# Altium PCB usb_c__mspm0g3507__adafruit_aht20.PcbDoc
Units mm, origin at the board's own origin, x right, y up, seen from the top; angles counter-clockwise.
Board outline 92 x 60 mm, 2 copper layers (Top, Bottom), stack 0 mm thick; 38 components, 33 nets, 190 pads, 53 vias.
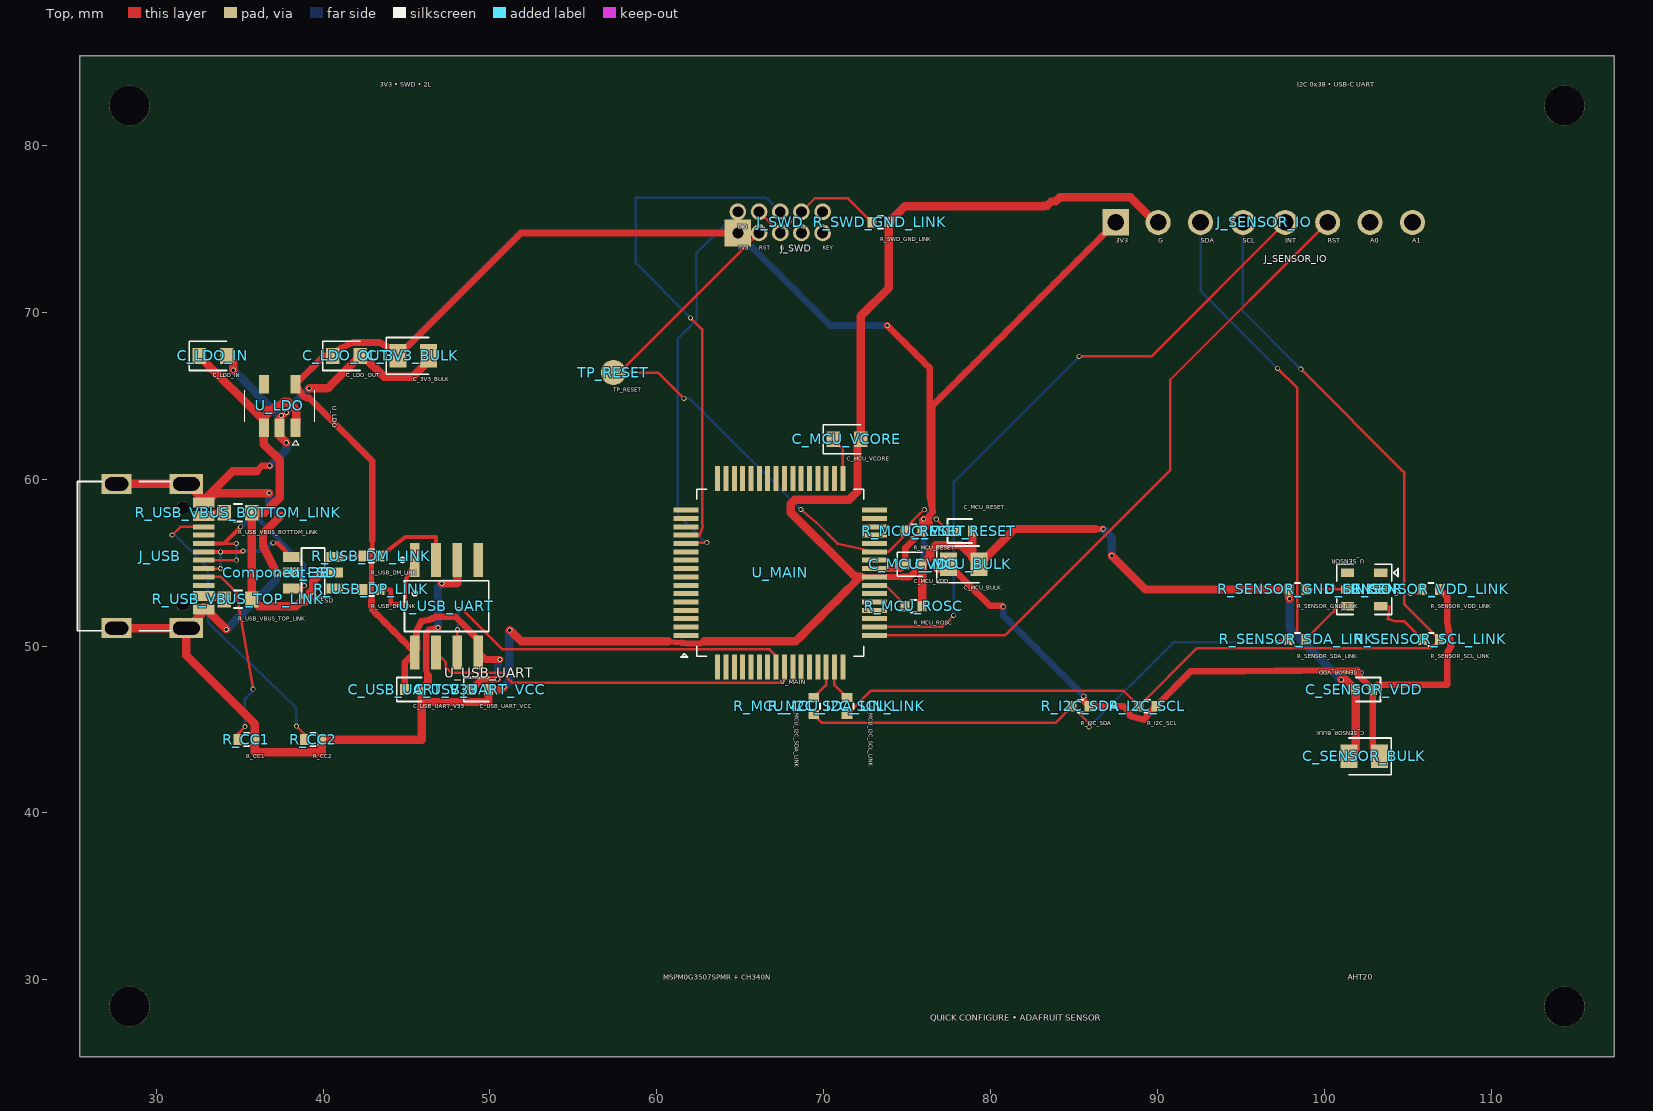
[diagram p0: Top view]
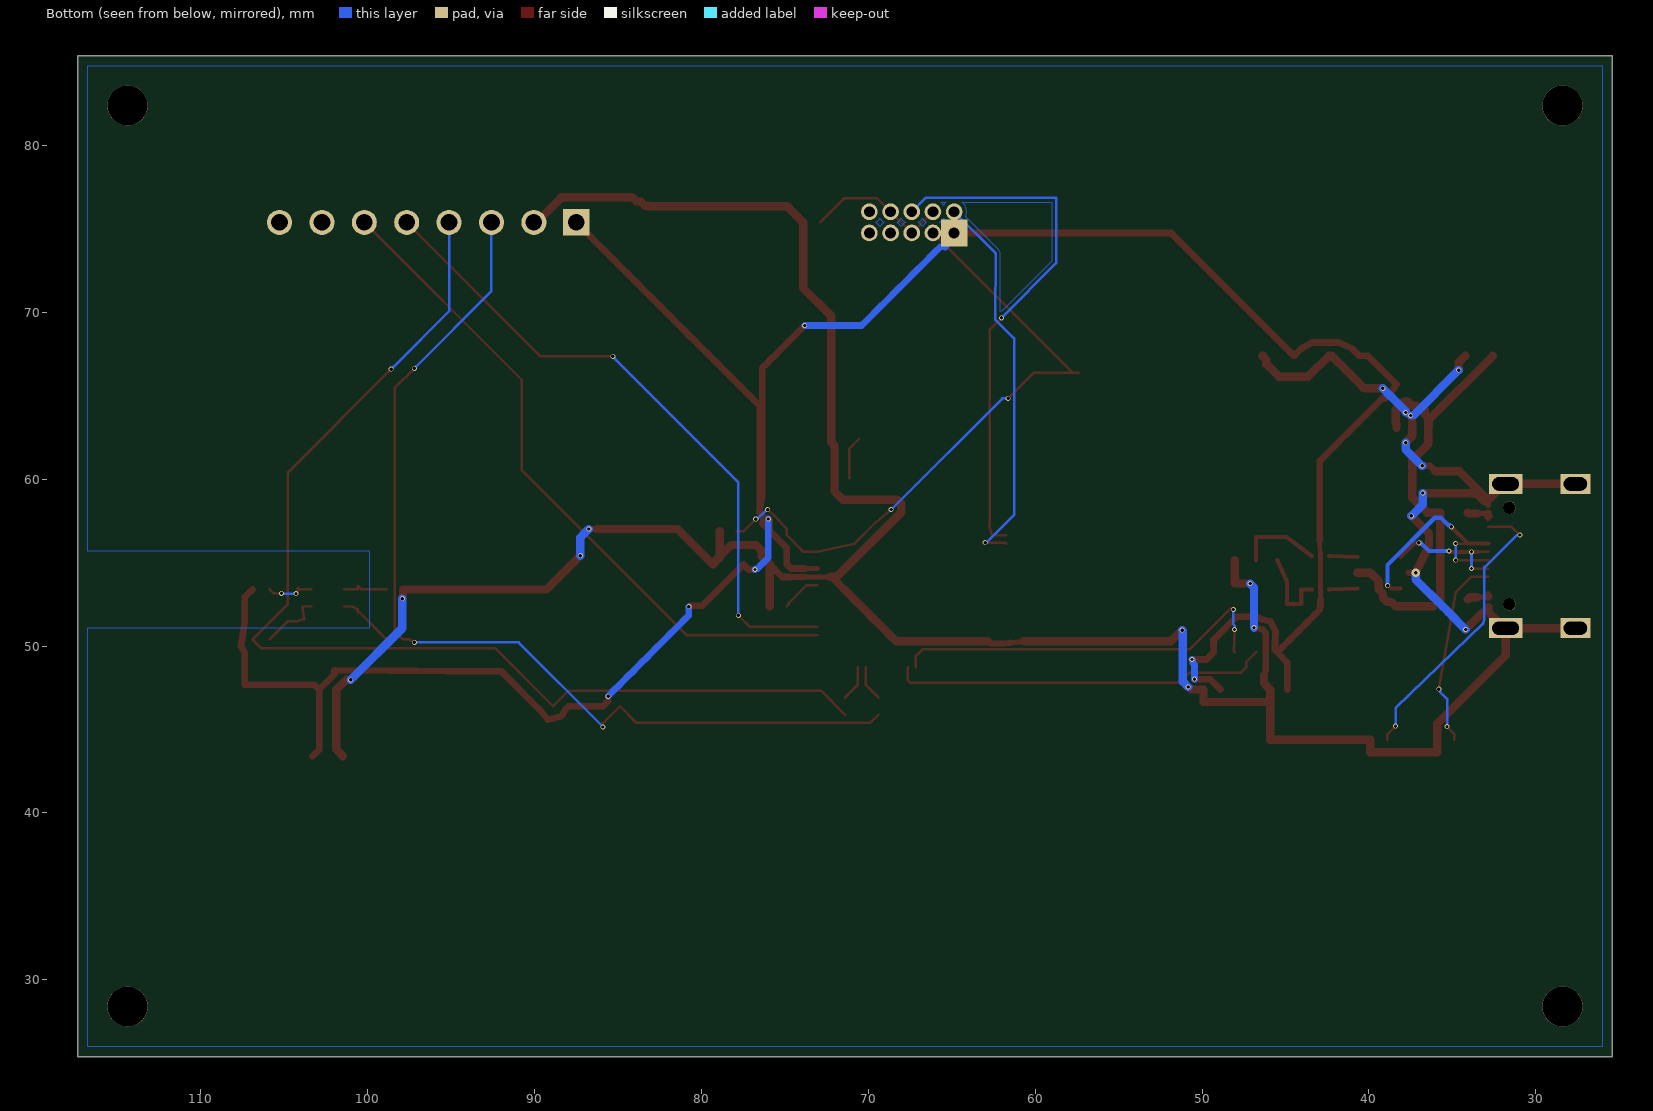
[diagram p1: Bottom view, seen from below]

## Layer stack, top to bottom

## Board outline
25.4,85.4 117.4,85.4 117.4,25.4 25.4,25.4

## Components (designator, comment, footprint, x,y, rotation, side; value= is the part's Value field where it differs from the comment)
C_3V3_BULK "" TSCIRCUIT-2.8500x1.4000mm 45.4,67.4 r0 top
C_LDO_IN "" TSCIRCUIT-2.4500x0.9500mm 33.4,67.4 r0 top
C_LDO_OUT "" TSCIRCUIT-2.4500x0.9500mm 41.4,67.4 r0 top
C_MCU_BULK "" TSCIRCUIT-2.8500x1.4000mm 78.4,54.9 r0 top
C_MCU_RESET "" TSCIRCUIT-1.5600x0.6400mm 78.4,56.9 r0 top
C_MCU_VCORE "" TSCIRCUIT-2.4500x0.9500mm 71.4,62.4 r0 top
C_MCU_VDD "" TSCIRCUIT-1.5600x0.6400mm 75.4,54.9 r0 top
C_SENSOR_BULK "" TSCIRCUIT-2.8500x1.4000mm 102.4,43.4 r180 top
C_SENSOR_VDD "" TSCIRCUIT-1.5600x0.6400mm 102.4,47.4 r180 top
C_USB_UART_V33 "" TSCIRCUIT-1.5600x0.6400mm 45.4,47.4 r0 top
C_USB_UART_VCC "" TSCIRCUIT-1.5600x0.6400mm 49.4,47.4 r0 top
Component-38 "" TSCIRCUIT-0.5000x0.5000mm 37.2,54.4 r0 top
J_SENSOR_IO "" TSCIRCUIT-19.2800x1.5000mm 96.4,75.4 r0 top
J_SWD "" TSCIRCUIT-6.0800x2.2700mm 67.4,75.4 r0 top
J_USB "" TSCIRCUIT-6.7732x9.8502mm 30.113,55.4 r90 top
R_CC1 "" TSCIRCUIT-1.5600x0.6400mm 35.4,44.4 r0 top
R_CC2 "" TSCIRCUIT-1.5600x0.6400mm 39.4,44.4 r0 top
R_I2C_SCL "" TSCIRCUIT-1.5600x0.6400mm 89.4,46.4 r0 top
R_I2C_SDA "" TSCIRCUIT-1.5600x0.6400mm 85.4,46.4 r0 top
R_MCU_I2C_SCL_LINK "" TSCIRCUIT-0.6400x1.5600mm 71.4,46.4 r270 top
R_MCU_I2C_SDA_LINK "" TSCIRCUIT-0.6400x1.5600mm 69.4,46.4 r270 top
R_MCU_RESET "" TSCIRCUIT-1.5600x0.6400mm 75.4,56.9 r0 top
R_MCU_ROSC "" TSCIRCUIT-1.5600x0.6400mm 75.4,52.4 r0 top
R_SENSOR_GND_LINK "" TSCIRCUIT-1.5600x0.6400mm 98.4,53.4 r0 top
R_SENSOR_SCL_LINK "" TSCIRCUIT-1.5600x0.6400mm 106.4,50.4 r0 top
R_SENSOR_SDA_LINK "" TSCIRCUIT-1.5600x0.6400mm 98.4,50.4 r0 top
R_SENSOR_VDD_LINK "" TSCIRCUIT-1.5600x0.6400mm 106.4,53.4 r0 top
R_SWD_GND_LINK "" TSCIRCUIT-1.5600x0.6400mm 73.4,75.4 r0 top
R_USB_DM_LINK "" TSCIRCUIT-1.5600x0.6400mm 42.9,55.4 r0 top
R_USB_DP_LINK "" TSCIRCUIT-1.5600x0.6400mm 42.9,53.4 r0 top
R_USB_VBUS_BOTTOM_LINK "" TSCIRCUIT-2.4500x0.9500mm 34.9,58 r0 top
R_USB_VBUS_TOP_LINK "" TSCIRCUIT-2.4500x0.9500mm 34.9,52.8 r0 top
TP_RESET "" TSCIRCUIT-1.5000x1.5000mm 57.4,66.4 r0 top
U_ESD "" TSCIRCUIT-3.6000x2.5000mm 39.4,54.4 r0 top
U_LDO "" TSCIRCUIT-2.5000x3.7000mm 37.4,64.4 r270 top
U_MAIN "" TSCIRCUIT-12.8000x12.8000mm 67.4,54.4 r0 top
U_SENSOR "" TSCIRCUIT-2.8000x2.5000mm 102.4,53.4 r0 top
U_USB_UART "" TSCIRCUIT-4.3840x7.5712mm 47.4,52.4 r0 top

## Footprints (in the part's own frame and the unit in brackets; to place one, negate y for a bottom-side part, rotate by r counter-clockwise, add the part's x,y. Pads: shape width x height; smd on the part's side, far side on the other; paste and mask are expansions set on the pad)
TSCIRCUIT-0.5000x0.5000mm [mm]
TSCIRCUIT-0.6400x1.5600mm [mm]
  rect 0.54x0.64 smd: 1(-0.51,0) 2(0.51,0)
  silkscreen extent -0.15,-0.38 0.15,0.38
TSCIRCUIT-1.5000x1.5000mm [mm]
  round 1.5 smd: 1(0,0)
TSCIRCUIT-1.5600x0.6400mm [mm]
  rect 0.54x0.64 smd: 1(-0.51,0) 2(0.51,0)
  silkscreen extent -0.98,-0.72 0.51,0.72
TSCIRCUIT-2.4500x0.9500mm [mm]
  rect 0.8x0.95 smd: 1(-0.825,0) 2(0.825,0)
  silkscreen extent -1.42,-0.87 0.82,0.87
TSCIRCUIT-2.5000x3.7000mm [mm]
  rect 1.1x0.6 smd: 1(1.3,0.95) 2(1.3,0) 3(1.3,-0.95) 4(-1.3,-0.95) 5(-1.3,0.95)
  silkscreen extent -0.95,-2.1 2.35,2.1
TSCIRCUIT-2.8000x2.5000mm [mm]
  rect 0.8x0.5 smd: 1(1,1) 2(1,0) 3(1,-1) 4(-1,-1) 5(-1,0) 6(-1,1)
  silkscreen extent -1.65,-1.5 2.02,1.5
TSCIRCUIT-2.8500x1.4000mm [mm]
  rect 1.025x1.4 smd: 1(-0.913,0) 2(0.913,0)
  silkscreen extent -1.63,-1.1 0.91,1.1
TSCIRCUIT-3.6000x2.5000mm [mm]
  rect 1x0.6 smd: 1(-1.3,-0.95) 2(-1.3,0) 3(-1.3,0.95) 4(1.3,0.95) 5(1.3,0) 6(1.3,-0.95)
  silkscreen extent -0.7,-1.49 0.7,1.49
TSCIRCUIT-4.3840x7.5712mm [mm]
  rect 0.574x2.036 smd: 1(-1.905,2.768) 2(-0.635,2.768) 3(0.635,2.768) 4(1.905,2.768) 5(1.905,-2.768) 6(0.635,-2.768) 7(-0.635,-2.768) 8(-1.905,-2.768)
  silkscreen extent -2.79,-1.52 2.53,2.92
TSCIRCUIT-6.0800x2.2700mm [mm]
  rect 1.6x1.6 hole 0.65: 1(-2.54,-0.635)
  round 1 hole 0.65: 2(-2.54,0.635) 3(-1.27,0.635) 4(0,0.635) 5(1.27,0.635) 6(2.54,0.635) 7(2.54,-0.635) 8(1.27,-0.635) 9(0,-0.635) 10(-1.27,-0.635)
TSCIRCUIT-6.7732x9.8502mm [mm]
  rect 0.3x1.3 smd: 1(-3.35,-2.737) 2(-3.05,-2.737) 3(-2.55,-2.737) 4(-2.25,-2.737) 5(-1.75,-2.737) 6(-1.25,-2.737) 7(-0.75,-2.737) 8(-0.25,-2.737) 9(0.25,-2.737) 10(0.75,-2.737) 11(1.25,-2.737) 12(1.75,-2.737) 13(2.55,-2.737) 14(2.25,-2.737) 15(3.35,-2.737) 16(3.05,-2.737)
  rect 1.2x2 hole 0.8 slot 1.6 at 90 deg: 17(-4.325,-1.693) 18(4.325,-1.693)
  rect 1.2x1.8 hole 0.8 slot 1.4 at 90 deg: 19(4.325,2.487) 20(-4.325,2.487)
  round 0.75 hole 0.75 unplated: NPTH-1(-2.9,-1.468) NPTH-2(2.9,-1.468)
  silkscreen extent -4.47,-0.75 4.47,4.83
TSCIRCUIT-12.8000x12.8000mm [mm]
  rect 1.5x0.3 smd: 1(-5.65,-3.75) 2(-5.65,-3.25) 3(-5.65,-2.75) 4(-5.65,-2.25) 5(-5.65,-1.75) 6(-5.65,-1.25) 7(-5.65,-0.75) 8(-5.65,-0.25) 9(-5.65,0.25) 10(-5.65,0.75) 11(-5.65,1.25) 12(-5.65,1.75) 13(-5.65,2.25) 14(-5.65,2.75) 15(-5.65,3.25) 16(-5.65,3.75) 33(5.65,3.75) 34(5.65,3.25) 35(5.65,2.75) 36(5.65,2.25) 37(5.65,1.75) 38(5.65,1.25) 39(5.65,0.75) 40(5.65,0.25) 41(5.65,-0.25) 42(5.65,-0.75) 43(5.65,-1.25) 44(5.65,-1.75) 45(5.65,-2.25) 46(5.65,-2.75) 47(5.65,-3.25) 48(5.65,-3.75)
  rect 0.3x1.5 smd: 17(-3.75,5.65) 18(-3.25,5.65) 19(-2.75,5.65) 20(-2.25,5.65) 21(-1.75,5.65) 22(-1.25,5.65) 23(-0.75,5.65) 24(-0.25,5.65) 25(0.25,5.65) 26(0.75,5.65) 27(1.25,5.65) 28(1.75,5.65) 29(2.25,5.65) 30(2.75,5.65) 31(3.25,5.65) 32(3.75,5.65) 49(3.75,-5.65) 50(3.25,-5.65) 51(2.75,-5.65) 52(2.25,-5.65) 53(1.75,-5.65) 54(1.25,-5.65) 55(0.75,-5.65) 56(0.25,-5.65) 57(-0.25,-5.65) 58(-0.75,-5.65) 59(-1.25,-5.65) 60(-1.75,-5.65) 61(-2.25,-5.65) 62(-2.75,-5.65) 63(-3.25,-5.65) 64(-3.75,-5.65)
  silkscreen extent -5.95,-5.05 5,5
TSCIRCUIT-19.2800x1.5000mm [mm]
  rect 1.6x1.6 hole 1: 1(-8.89,0)
  round 1.5 hole 1: 2(-6.35,0) 3(-3.81,0) 4(-1.27,0) 5(1.27,0) 6(3.81,0) 7(6.35,0) 8(8.89,0)

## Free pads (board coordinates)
  round 2.4 hole 2.4 unplated: NPTH-3(28.4,28.4) NPTH-4(114.4,28.4) NPTH-5(28.4,82.4) NPTH-6(114.4,82.4)

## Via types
v1: diameter 0.3, hole 0.2, Top to Bottom, 52 vias
v2: diameter 0.5, hole 0.2, Top to Bottom, 1 vias

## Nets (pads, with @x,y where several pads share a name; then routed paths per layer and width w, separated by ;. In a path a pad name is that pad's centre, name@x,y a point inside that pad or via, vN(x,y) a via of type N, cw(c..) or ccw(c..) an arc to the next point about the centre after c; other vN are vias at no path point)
".J_SWD > .pin2 to .U_MAIN > .pin12": J_SWD.2 U_MAIN.12 | length 23.4
  Top w0.15: U_MAIN.12 61.8,56.2 v1(63,56.2)
  Bottom w0.15: v1(63,56.2) 62.989,56.211 62.913,56.211 61.261,57.863 61.261,58.027 61.262,68.446 62.382,69.559 62.378,73.553 J_SWD.2
".J_SWD > .pin4 to .U_MAIN > .pin13": J_SWD.4 U_MAIN.13 | length 31.7
  Top w0.15: U_MAIN.13 62.496,56.65 62.568,56.628 62.763,57.17 62.72,57.338 62.72,68.98 v1(62.021,69.679)
  Bottom w0.15: v1(62.021,69.679) 61.968,69.732 58.745,72.955 58.745,76.868 66.567,76.868 J_SWD.4
".U_MAIN > .pin42 to .R_MCU_ROSC > .pin1": R_MCU_ROSC.1 U_MAIN.42 | length 2.4
  Top w0.15: U_MAIN.42 73.719,53.65 74.769,52.6 74.769,52.521 R_MCU_ROSC.1
AHT_GND_LOCAL: R_SENSOR_GND_LINK.2 U_SENSOR.5 | length 2.8
  Top w0.15: R_SENSOR_GND_LINK.2 100.377,53.4 100.577,53.6 100.61,53.6 100.61,53.4 100.64,53.4 U_SENSOR.5
AHT_SCL_LOCAL: R_SENSOR_SCL_LINK.1 U_SENSOR.3 | length 3.9
  Top w0.15: U_SENSOR.3 103.934,52.364 103.8,51.61 103.913,51.61 104.227,51.496 ; 104.227,51.497 104.793,51.497 R_SENSOR_SCL_LINK.1
AHT_SDA_LOCAL: R_SENSOR_SDA_LINK.2 U_SENSOR.4 | length 3.4
  Top w0.15: R_SENSOR_SDA_LINK.2 98.91,50.438 100.474,52.002 100.61,52.05 100.61,52.2 100.902,52.364 U_SENSOR.4
AHT_VDD_LOCAL: R_SENSOR_VDD_LINK.1 U_SENSOR.2 | length 3
  Top w0.15: U_SENSOR.2 104.02,53.4 104.19,53.4 104.19,53.495 104.19,53.3 v1(104.305,53.149) ; v1(105.173,53.17) 105.66,53.17 R_SENSOR_VDD_LINK.1
  Bottom w0.15: v1(104.305,53.149) 105.055,53.149 105.151,53.149 v1(105.173,53.17)
GND: C_3V3_BULK.2 C_LDO_IN.2 C_LDO_OUT.2 C_MCU_BULK.2 C_MCU_RESET.2 C_MCU_VCORE.2 C_MCU_VDD.2 C_SENSOR_BULK.2 C_SENSOR_VDD.2 C_USB_UART_V33.2 C_USB_UART_VCC.2 J_SENSOR_IO.2 J_USB.1 J_USB.2 J_USB.15 J_USB.16 J_USB.17 J_USB.18 J_USB.19 J_USB.20 R_CC1.2 R_CC2.2 R_MCU_ROSC.2 R_SENSOR_GND_LINK.1 R_SWD_GND_LINK.2 U_ESD.2 U_LDO.2 U_MAIN.41 U_USB_UART.3 | length 212.6
  Top w0.275: J_USB.16 J_USB.15@33.089,58.69
  Top w0.3: J_USB.1@32.699,51.9 J_USB.1 J_USB.1@32.849,52.2 ; J_USB.15@32.699,58.9 J_USB.15 ; J_USB.2 32.999,52.2 33.187,52.013 J_USB.1@33.189,52.013 ; J_USB.16@32.849,58.6 J_USB.15 ; J_USB.15@32.999,58.9 J_USB.15 ; U_MAIN.41@73.8,54.15 73.706,54.15 73.612,54.15 73.519,54.15 73.425,54.15 73.331,54.15 73.237,54.15 73.144,54.15 U_MAIN.41 ; U_MAIN.41 72.627,54.15 72.3,54.15 72.62,54.15 U_MAIN.41
  Top w0.312: 60.695,50.298 60.728,50.265 61.108,50.232
  Top w0.325: J_USB.16 J_USB.16@32.849,58.6 ; 61.108,50.232 61.488,50.199
  Top w0.35: U_LDO.2@37.4,63.6 37.687,63.887 v1(37.8,64) ; v1@37.4,63.725 v1(37.5,63.825) ; 86.27,57.022 v1(86.754,57.023)
  Top w0.375: U_LDO.2@37.4,63.376 37.4,63.652 v1@37.4,63.725 ; 46.289,48.237 46.181,48.556 46.181,50.806 46.369,50.994 v1(46.883,51.106) ; 61.488,50.199 61.869,50.166 62.259,50.166 62.65,50.166 62.844,50.298 ; U_MAIN.41@73.8,54.15 74.253,54.15 74.707,54.15
  Top w0.4: 36.019,60.491 36.341,60.813 v1(36.808,60.804) ; 37.2,54.4 U_ESD.2@37.6,54.4 ; 74.707,54.15 75.16,54.15 75.41,54.4 75.66,54.65 C_MCU_VDD.2
  Top w0.437: v1(36.765,59.175) v1(36.765,59.175)
  Top w0.45: U_LDO.2 U_LDO.2@37.4,63.6 ; 71.489,53.45 71.839,53.8 72.189,54.15 72.3,54.15
  Top w0.475: 72.205,54.15 72.3,54.15
  Top w0.5: J_USB.20 J_USB.17 ; J_USB.19 J_USB.18 31.874,59.725 32.474,59.125 32.699,58.9 ; 32.699,51.9 32.474,51.675 31.874,51.075 J_USB.17 ; J_USB.1@32.849,52.2 J_USB.2 ; 32.999,58.9 34.59,60.491 36.019,60.491 ; J_USB.15@33.089,58.69 33.329,58.93 33.573,59.173 35.852,59.173 v1(36.765,59.175) ; J_USB.1@33.189,52.013 v1(34.201,51.001) ; C_LDO_IN.2 34.423,67.202 34.621,67.004 v1(34.621,66.54) ; 37.2,54.4 36.4,56 36.4,56.752 v1(37.459,57.811) ; U_LDO.2@37.4,63.376 U_LDO.2 37.4,62.6 37.75,62.25 v1(37.8,62.2) ; v1(39.167,65.456) 39.538,65.456 39.91,65.456 40.281,65.456 40.605,65.78 40.929,66.104 41.253,66.428 41.577,66.752 41.901,67.076 C_LDO_OUT.2 42.4,67.4 43.65,66.15 45.4,66.15 46.15,66.9 46.15,67.15 46.4,67.4 C_3V3_BULK.2 ; 46.289,48.237 46.291,47.787 46.1,47.593 C_USB_UART_V33.2 ; v1(47.115,53.757) 48.035,53.757 U_USB_UART.3 ; v1(50.829,47.553) 50.705,47.429 50.648,47.429 50.619,47.4 50.265,47.4 C_USB_UART_VCC.2 49.91,46.65 45.91,46.65 C_USB_UART_V33.2 ; v1(51.194,50.962) 51.526,50.63 51.858,50.298 60.695,50.298 ; 62.844,50.298 63.344,50.298 63.843,50.298 64.342,50.298 64.842,50.298 65.341,50.298 65.84,50.298 66.34,50.298 66.839,50.298 67.338,50.298 67.838,50.298 68.337,50.298 68.687,50.648 69.038,50.998 69.388,51.348 69.738,51.699 70.088,52.049 70.438,52.399 70.789,52.749 71.139,53.099 71.489,53.45 ; 72.205,54.15 71.994,54.15 71.947,54.197 71.853,54.197 68.025,58.025 68.025,58.525 68.275,58.775 71.525,58.775 72.025,59.275 72.025,62.025 72.225,62.225 C_MCU_VCORE.2 72.225,62.892 72.225,63.384 72.225,63.876 72.225,64.368 72.225,64.86 72.225,65.352 72.225,65.844 72.225,66.336 72.225,66.828 72.225,67.32 72.225,67.812 72.225,68.303 72.225,68.795 72.225,69.287 72.225,69.779 73.91,71.464 R_SWD_GND_LINK.2 74.232,75.722 74.554,76.044 74.876,76.366 74.951,76.366 75.438,76.366 75.925,76.366 76.413,76.366 76.9,76.366 77.387,76.366 77.875,76.366 78.362,76.366 78.849,76.366 79.337,76.366 79.824,76.366 80.311,76.366 80.799,76.366 81.286,76.366 81.773,76.366 82.261,76.366 82.748,76.366 83.235,76.366 83.202,76.4 83.4,76.4 83.65,76.65 83.9,76.65 84.15,76.9 88.4,76.9 89.9,75.4 J_SENSOR_IO.2 ; R_MCU_ROSC.2 C_MCU_VDD.2 75.9,54.9 76.4,55.4 76.4,55.733 76.733,56.067 78.233,56.067 79.313,54.988 C_MCU_BULK.2 ; C_MCU_RESET.2 78.91,55.303 C_MCU_BULK.2 ; 86.27,57.022 85.786,57.022 81.434,57.022 C_MCU_BULK.2 ; v1(87.265,55.423) 87.411,55.277 89.288,53.4 96.454,53.4 96.932,53.4 97.411,53.4 R_SENSOR_GND_LINK.1 97.89,52.892 v1(97.937,52.845) ; v1(101.032,47.978) 101.312,47.978 C_SENSOR_VDD.2 101.89,43.803 C_SENSOR_BULK.2 ; J_USB.17 31.806,49.444 35.908,45.341 35.909,44.871 R_CC1.2 35.91,43.65 39.91,43.65 R_CC2.2 40.41,44.4 40.91,44.4 45.91,44.4 C_USB_UART_V33.2
  Bottom w0.5: v1(34.201,51.001) 34.262,51.062 34.589,51.389 34.915,51.715 35.241,52.041 35.568,52.368 35.894,52.694 36.221,53.021 36.547,53.347 36.874,53.674 37.2,54 37.2,54.4 ; v1(34.621,66.54) 37.336,63.825 v1(37.5,63.825) ; v1(36.765,59.175) 36.765,58.505 v1(37.459,57.811) ; v1(36.808,60.804) 37.8,61.796 v1(37.8,62.2) ; v1(37.8,64) 37.8,64.085 38.138,64.423 38.476,64.761 38.815,65.099 39.153,65.437 39.153,65.442 v1(39.167,65.456) ; v1(46.883,51.106) 46.883,51.59 46.883,52.074 46.883,52.557 46.883,53.041 46.883,53.525 v1(47.115,53.757) ; v1(50.829,47.553) 51.152,47.876 51.152,48.31 51.152,48.745 51.152,49.179 51.152,49.614 51.152,50.048 51.152,50.483 51.152,50.918 51.152,50.92 v1(51.194,50.962) ; v1(86.754,57.023) 86.799,56.978 87.032,56.745 87.265,56.512 87.265,56.149 87.265,55.786 v1(87.265,55.423) ; v1(97.937,52.845) 97.937,51.073 v1(101.032,47.978)
MAIN_RESET: C_MCU_RESET.1 J_SWD.10 R_MCU_RESET.1 TP_RESET.1 U_MAIN.38 | length 38.8
  Top w0.15: v1(61.625,64.85) 61.552,64.923 60.075,66.4 TP_RESET.1 57.765,66.4 J_SWD.10 ; v1(68.634,58.195) 69.555,57.424 70.823,56.15 U_MAIN.38 73.889,55.65 74.889,56.651 R_MCU_RESET.1@74.889,56.899 ; R_MCU_RESET.1 74.89,57.03 75.633,57.814 v1(76.032,58.178) ; v1(76.75,57.615) 76.733,57.635 77.468,56.9 C_MCU_RESET.1
  Bottom w0.15: v1(61.625,64.85) 61.971,64.85 68.557,58.264 v1(68.634,58.195) ; v1(76.032,58.178) 76.114,58.102 76.172,58.102 76.635,57.639 v1(76.75,57.615)
MCU_I2C_SCL_LOCAL: R_MCU_I2C_SCL_LINK.1 U_MAIN.50 | length 2.2
  Top w0.15: U_MAIN.50 70.65,47.66 R_MCU_I2C_SCL_LINK.1
MCU_I2C_SDA_LOCAL: R_MCU_I2C_SDA_LINK.1 U_MAIN.51 | length 2.2
  Top w0.15: R_MCU_I2C_SDA_LINK.1 70.15,47.66 U_MAIN.51
MSPM0_VCORE: C_MCU_VCORE.1 U_MAIN.32 | length 2.6
  Top w0.15: C_MCU_VCORE.1 71.15,61.825 U_MAIN.32
SENSOR_ADDR0: J_SENSOR_IO.7
SENSOR_ADDR1: J_SENSOR_IO.8
SENSOR_INT: J_SENSOR_IO.5 U_MAIN.47 | length 39.4
  Top w0.15: U_MAIN.47 77.094,51.15 77.767,51.823 v1(77.795,51.851) ; v1(85.312,67.373) 89.643,67.373 J_SENSOR_IO.5
  Bottom w0.15: v1(77.795,51.851) 77.795,59.816 85.243,67.265 85.243,67.304 v1(85.312,67.373)
SENSOR_RESET: J_SENSOR_IO.6 U_MAIN.48 | length 40.6
  Top w0.15: U_MAIN.48 80.875,50.647 90.78,60.549 90.776,65.966 J_SENSOR_IO.6
SENSOR_SCL: J_SENSOR_IO.4 R_I2C_SCL.1 R_MCU_I2C_SCL_LINK.2 R_SENSOR_SCL_LINK.2 | length 68
  Top w0.15: R_MCU_I2C_SCL_LINK.2 72.843,47.333 87.777,47.336 87.957,47.333 R_I2C_SCL.1 92.36,49.87 106.38,49.87 R_SENSOR_SCL_LINK.2 104.791,52.519 104.791,52.521 104.791,60.409 v1(98.6,66.6)
  Bottom w0.15: J_SENSOR_IO.4 95.13,70.071 98.433,66.768 98.433,66.767 v1(98.6,66.6)
SENSOR_SDA: J_SENSOR_IO.3 R_I2C_SDA.1 R_MCU_I2C_SDA_LINK.2 R_SENSOR_SDA_LINK.1 | length 59.6
  Top w0.15: R_MCU_I2C_SDA_LINK.2 69.891,45.399 83.889,45.399 R_I2C_SDA.1 85.91,45.38 v1(85.91,45.153) ; v1(97.215,50.229) 97.313,50.327 97.42,50.327 97.493,50.4 R_SENSOR_SDA_LINK.1 98.4,50.91 98.4,50.938 98.4,65.466 v1(97.215,66.651)
  Bottom w0.15: v1(85.91,45.153) 85.948,45.191 85.948,45.214 90.963,50.229 v1(97.215,50.229) ; J_SENSOR_IO.3 92.59,71.276 97.098,66.768 v1(97.215,66.651)
swd-ground-1-to-2: J_SWD.3 J_SWD.5 J_SWD.9 R_SWD_GND_LINK.1 | length 8.8
  Top w0.15: J_SWD.3 J_SWD.9 J_SWD.5 69.481,76.846 71.471,76.846 71.471,76.819 R_SWD_GND_LINK.1
UART_MSP_RX: U_MAIN.57 U_USB_UART.6 | length 23.5
  Top w0.15: U_USB_UART.6 48.092,49.689 v1(48.051,50.998) ; v1(48.121,52.195) 48.194,52.262 48.287,52.262 50.749,49.8 66.767,49.802 67.151,49.417 U_MAIN.57
  Bottom w0.15: v1(48.051,50.998) 48.03,51.101 48.03,51.222 48.116,51.307 v1(48.121,52.195)
UART_MSP_TX: U_MAIN.56 U_USB_UART.7 | length 22.7
  Top w0.15: U_USB_UART.7 47.363,49.034 47.363,48.717 47.668,48.413 50.736,48.413 51.329,47.82 67.49,47.807 67.65,47.981 U_MAIN.56
usb-dm-device: R_USB_DM_LINK.1 U_ESD.4 | length 1.7
  Top w0.25: U_ESD.4 R_USB_DM_LINK.1
usb-dm-port-tie: J_USB.7 J_USB.9 U_ESD.3 | length 8.9
  Top w0.15: J_USB.7 v1(33.85,54.65) ; J_USB.9@33.35,55.65 33.318,55.65 33.224,55.65 33.13,55.65 33.037,55.65 32.943,55.65 J_USB.9 v1(33.85,55.65)
  Top w0.175: J_USB.9@33.35,55.65 J_USB.9@33.412,55.65
  Top w0.212: J_USB.9@33.412,55.65 33.505,55.65
  Top w0.25: 33.505,55.65 33.599,55.65 35.067,55.65 35.089,55.673 35.173,55.673 v1(35.2,55.7) ; v1(37.004,56.192) 37.25,56.2 U_ESD.3
  Bottom w0.15: v1(33.85,54.65) v1(33.85,55.65)
  Bottom w0.25: v1(35.2,55.7) 36.406,55.7 36.953,56.247 v1(37.004,56.192)
usb-dm-uart: R_USB_DM_LINK.2 U_USB_UART.2 | length 5.1
  Top w0.25: R_USB_DM_LINK.2 44.95,56.55 46.765,56.55 U_USB_UART.2
usb-dp-device: R_USB_DP_LINK.1 U_ESD.6 | length 1.7
  Top w0.25: U_ESD.6 R_USB_DP_LINK.1
usb-dp-port-tie: J_USB.8 J_USB.10 U_ESD.1 | length 14.8
  Top w0.15: J_USB.8 v1(34.8,55.15) ; J_USB.10 v1(34.8,56.15)
  Top w0.25: J_USB.10 34.059,56.15 v1(35.062,57.153) ; U_ESD.1 38.65,53.45 38.791,53.591 38.844,53.591 v1(38.879,53.626)
  Bottom w0.15: v1(34.8,55.15) v1(34.8,56.15)
  Bottom w0.25: v1(35.062,57.153) 35.157,57.248 35.234,57.248 35.678,57.692 36.053,57.696 38.882,54.865 v1(38.879,53.626)
usb-dp-uart: R_USB_DP_LINK.2 U_USB_UART.1 | length 5.1
  Top w0.25: R_USB_DP_LINK.2 44.05,53.4 44.05,52.53 44.9,52.53 44.9,53.85 U_USB_UART.1
USB_CC1: J_USB.6 R_CC1.1 | length 11.6
  Top w0.15: J_USB.6 33.87,54.15 34.785,53.234 v1(35.803,47.427) ; R_CC1.1 34.89,44.747 35.313,45.17 v1(35.318,45.175)
  Bottom w0.15: v1(35.318,45.175) 35.318,46.835 35.735,47.251 35.735,47.358 v1(35.803,47.427)
USB_CC2: J_USB.12 R_CC2.1 | length 17.8
  Top w0.15: v1(30.956,56.662) 31.444,57.15 J_USB.12 ; v1(38.404,45.206) 38.409,45.201 38.89,44.72 R_CC2.1
  Bottom w0.15: v1(30.956,56.662) 31.12,56.662 33.035,54.747 33.076,54.747 33.076,51.63 33.15,51.35 38.404,46.302 v1(38.404,45.206)
USB_VBUS_BOTTOM_LOCAL: J_USB.13 J_USB.14 R_USB_VBUS_BOTTOM_LINK.1 | length 1.5
  Top w0.3: J_USB.14 J_USB.14@32.849,57.8 ; J_USB.13 32.927,57.95 33.005,57.95 33.083,57.95 33.161,57.95 33.239,57.95 33.317,57.95 33.394,57.95 33.472,57.95 33.499,57.95
  Top w0.475: J_USB.13@32.849,57.8 J_USB.13 ; 33.499,57.95 R_USB_VBUS_BOTTOM_LINK.1@33.762,57.95
  Top w0.5: R_USB_VBUS_BOTTOM_LINK.1@33.762,57.95 34.025,57.95 R_USB_VBUS_BOTTOM_LINK.1
USB_VBUS_TOP_LOCAL: J_USB.3 J_USB.4 R_USB_VBUS_TOP_LINK.1 | length 1.6
  Top w0.3: J_USB.4 32.849,53 J_USB.3 32.945,52.958 33.032,52.939 33.499,52.939
  Top w0.5: 33.499,52.939 33.675,52.939 33.936,52.939 R_USB_VBUS_TOP_LINK.1
VBUS5: C_LDO_IN.1 R_USB_VBUS_BOTTOM_LINK.2 R_USB_VBUS_TOP_LINK.2 U_ESD.5 U_LDO.1 U_LDO.3 | length 28.9
  Top w0.5: C_LDO_IN.1 36.45,63.525 U_LDO.3 ; U_LDO.1 38.35,63.35 38.4,63.4 38.4,64.15 37.9,64.65 37.65,64.65 37.4,64.4 37.15,64.4 36.9,64.15 36.65,64.15 36.65,63.9 36.4,63.65 36.4,63.15 U_LDO.3 ; U_ESD.5 39.9,54.4 39.4,53.9 39.4,53.4 39.15,53.15 39.15,52.9 38.9,52.65 38.65,52.65 38.4,52.4 36.15,52.4 35.9,52.65 35.9,52.625 35.992,52.533 R_USB_VBUS_TOP_LINK.2 R_USB_VBUS_BOTTOM_LINK.2 36.5,58 37.4,58.9 37.4,61.15 36.45,62.1 U_LDO.3
VCC_3V3: C_3V3_BULK.1 C_LDO_OUT.1 C_MCU_BULK.1 C_MCU_VDD.1 C_SENSOR_BULK.1 C_SENSOR_VDD.1 C_USB_UART_V33.1 C_USB_UART_VCC.1 J_SENSOR_IO.1 J_SWD.1 R_I2C_SCL.2 R_I2C_SDA.2 R_MCU_RESET.2 R_SENSOR_VDD_LINK.2 U_LDO.5 U_MAIN.40 U_USB_UART.5 U_USB_UART.8 | length 167.8
  Top w0.25: 42.9,55.65 42.944,55.934 42.944,56.332
  Top w0.275: 42.9,52.796 42.9,53.192 42.9,53.588 42.9,53.983 42.9,54.379 42.9,54.775 42.9,55.067 42.9,55.358 42.9,55.65
  Top w0.3: U_MAIN.40 73.15,54.65 73.25,54.65 73.35,54.65 73.45,54.65 73.55,54.65 73.65,54.65 73.75,54.65 U_MAIN.40@73.8,54.65
  Top w0.325: 85.6,46.71 v1(85.6,46.996)
  Top w0.375: 42.944,56.332 42.944,56.729 ; 76.296,57.717 76.3,57.792 ; 76.3,57.442 76.3,57.792 ; 76.3,57.792 76.533,58.025 76.3,57.792
  Top w0.387: 49.509,48.019 49.801,48.019 50.092,48.019 50.383,48.019 v1@50.451,48.019 ; 76.3,57.442 76.367,57.357
  Top w0.4: 42.9,52.796 42.9,52.4 42.944,52.353 42.944,52.183 43.199,51.928 43.454,51.673 43.709,51.418 43.965,51.163 44.22,50.907 44.475,50.652 44.73,50.397 44.985,50.142 45.24,49.887 U_USB_UART.8 ; 42.944,56.729 42.944,57.127 42.944,57.525 42.944,57.923 42.944,58.321 42.944,58.719 42.944,59.117 42.944,59.514 42.944,59.912 42.944,60.31 42.944,60.708 42.944,61.106 42.674,61.376 42.404,61.646 42.133,61.917 41.863,62.187 41.593,62.457 41.323,62.727 41.052,62.998 40.782,63.268 40.512,63.538 40.242,63.808 39.971,64.079 39.701,64.349 39.431,64.619 39.161,64.889 39,64.85 38.8,65 U_LDO.5 40.05,67.4 C_LDO_OUT.1 40.795,67.622 41.016,67.843 41.8,68.2 43.4,68.2 44.047,67.841 44.267,67.62 C_3V3_BULK.1 51.853,74.765 J_SWD.1 ; C_USB_UART_V33.1 44.89,49.027 U_USB_UART.8 ; C_USB_UART_VCC.1 49.096,47.606 49.303,47.813 49.509,48.019 ; v1@50.451,48.019 v1(50.457,48.025) ; v1(50.6,49.2) 50.312,49.2 50.025,49.2 49.737,49.2 49.521,49.416 U_USB_UART.5 49.318,50.378 47.946,51.764 46.778,51.76 46.368,51.581 45.9,51.5 45.6,50.9 45.647,49.784 U_USB_UART.8 ; U_MAIN.40@73.8,54.65 73.85,54.65 74.64,54.65 C_MCU_VDD.1 74.89,55.88 R_MCU_RESET.2 ; v1(73.816,69.217) 74.071,68.962 74.326,68.707 74.581,68.452 74.837,68.197 75.092,67.941 75.347,67.686 75.602,67.431 75.857,67.176 76.112,66.921 76.368,66.666 76.368,66.282 76.368,65.899 76.368,65.515 76.368,65.131 76.369,64.748 76.369,64.364 76.369,63.981 76.369,63.597 76.369,63.214 76.37,62.83 76.37,62.446 76.37,62.063 76.37,61.679 76.37,61.296 76.371,60.912 76.371,60.528 76.371,60.145 76.371,59.761 76.372,59.378 76.372,58.994 76.426,58.671 76.479,58.348 76.533,58.025 76.512,58.356 76.491,58.687 76.492,59.068 76.494,59.448 76.495,59.829 76.496,60.21 76.497,60.591 76.498,60.972 76.5,61.353 76.501,61.733 76.502,62.114 76.503,62.495 76.505,62.876 76.506,63.257 76.507,63.638 76.508,64.019 76.509,64.399 76.791,64.681 77.073,64.963 77.356,65.246 77.638,65.528 77.92,65.81 78.202,66.092 78.484,66.374 78.766,66.656 79.048,66.938 79.33,67.22 79.612,67.502 79.894,67.784 80.176,68.066 80.458,68.348 80.74,68.63 81.022,68.912 81.305,69.195 81.587,69.477 81.869,69.759 82.151,70.041 82.433,70.323 82.715,70.605 82.997,70.887 83.279,71.169 83.561,71.451 83.843,71.733 84.125,72.015 84.407,72.297 84.689,72.579 84.971,72.861 85.253,73.143 85.536,73.426 85.818,73.708 86.1,73.99 86.382,74.272 86.664,74.554 86.946,74.836 87.228,75.118 J_SENSOR_IO.1 ; v1(76,57.62) 75.994,57.614 75.91,57.53 75.91,57.215 R_MCU_RESET.2 ; 76.296,57.717 76.103,57.509 75.91,57.302 75.91,57.101 R_MCU_RESET.2 ; 76.367,57.357 76.139,57.129 R_MCU_RESET.2 ; v1(76.791,54.592) 77.18,54.592 77.334,54.746 C_MCU_BULK.1 77.763,54.624 78.039,54.348 78.315,54.073 78.591,53.797 78.866,53.521 79.142,53.245 79.418,52.97 79.694,52.694 79.969,52.418 80.339,52.418 80.709,52.418 v1(80.762,52.365) ; 85.6,46.71 85.755,46.555 R_I2C_SDA.2 86.255,46.4 86.6,46.4 86.945,46.4 87.29,46.4 87.635,46.4 87.98,46.4 88.132,46.248 88.4,45.8 89.2,45.6 89.587,46.077 89.748,46.238 R_I2C_SCL.2 91.981,48.478 101.993,48.55 101.993,48.317 C_SENSOR_VDD.1 ; C_SENSOR_BULK.1 102.91,43.803 C_SENSOR_VDD.1 ; R_SENSOR_VDD_LINK.2 107.14,53.177 107.37,52.955 107.37,52.578 107.37,52.201 107.37,51.825 107.37,51.448 107.6,50 107.37,49.564 107.37,49.187 107.37,48.81 107.37,48.433 107.37,48.057 107.37,47.68 106.99,47.68 106.61,47.68 106.23,47.68 105.85,47.68 105.47,47.68 105.09,47.68 104.71,47.68 104.33,47.68 103.95,47.68 103.57,47.68 103.19,47.68 C_SENSOR_VDD.1
  Bottom w0.4: v1(50.457,48.025) 50.457,48.312 50.457,48.599 50.457,48.886 50.554,48.984 50.554,49.154 v1(50.6,49.2) ; J_SWD.1 65.4,73.9 65.692,73.933 65.969,73.656 66.246,73.379 66.523,73.102 66.801,72.824 67.078,72.547 67.355,72.27 67.632,71.993 67.91,71.715 68.187,71.438 68.464,71.161 68.741,70.884 69.019,70.606 69.296,70.329 69.573,70.052 69.85,69.775 70.127,69.498 70.405,69.22 70.783,69.22 71.162,69.22 71.541,69.22 71.919,69.22 72.298,69.22 72.677,69.22 73.055,69.22 73.434,69.22 73.813,69.22 v1(73.816,69.217) ; v1(76,57.62) 76,57.232 76,56.843 76,56.455 76,56.066 76,55.678 76,55.289 76.216,55.073 76.433,54.857 76.649,54.64 76.742,54.64 v1(76.791,54.592) ; v1(80.762,52.365) 80.762,52.102 80.762,51.839 81.042,51.559 81.321,51.279 81.601,51 81.88,50.72 82.16,50.441 82.44,50.161 82.719,49.881 82.999,49.602 83.279,49.322 83.558,49.042 83.838,48.763 84.117,48.483 84.397,48.204 84.677,47.924 84.956,47.644 85.236,47.365 v1@85.516,47.085 ; v1@85.516,47.084 v1(85.6,46.996)
pads on no net: J_SWD.6 J_SWD.7 J_SWD.8 J_USB.5 J_USB.11 J_USB.NPTH-1 J_USB.NPTH-2 U_LDO.4 U_MAIN.1 U_MAIN.2 U_MAIN.3 U_MAIN.4 U_MAIN.5 U_MAIN.6 U_MAIN.7 U_MAIN.8 U_MAIN.9 U_MAIN.10 U_MAIN.11 U_MAIN.14 U_MAIN.15 U_MAIN.16 U_MAIN.17 U_MAIN.18 U_MAIN.19 U_MAIN.20 U_MAIN.21 U_MAIN.22 U_MAIN.23 U_MAIN.24 U_MAIN.25 U_MAIN.26 U_MAIN.27 U_MAIN.28 U_MAIN.29 U_MAIN.30 U_MAIN.31 U_MAIN.33 U_MAIN.34 U_MAIN.35 U_MAIN.36 U_MAIN.37 U_MAIN.39 U_MAIN.43 U_MAIN.44 U_MAIN.45 U_MAIN.46 U_MAIN.49 U_MAIN.52 U_MAIN.53 U_MAIN.54 U_MAIN.55 U_MAIN.58 U_MAIN.59 U_MAIN.60 U_MAIN.61 U_MAIN.62 U_MAIN.63 U_MAIN.64 U_SENSOR.1 U_SENSOR.6 U_USB_UART.4
copper on no net:
  other v2: 37.2,54.4

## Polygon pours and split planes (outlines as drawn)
GND on Bottom (solid): 116.8,84.8 26,84.8 26,26 116.8,26 116.8,51.1 100.2,51.1 99.9,51.1 99.9,51.4 99.9,55.1 99.9,55.7 100.5,55.7 116.8,55.7
GND on Bottom (solid): 65.633,76.593 65.357,76.593 65.39,76.565 65.484,76.452 65.495,76.43 65.506,76.452 65.6,76.565
GND on Bottom (solid): 65.495,75.64 65.484,75.618 65.399,75.515 65.591,75.515 65.506,75.618
GND on Bottom (solid): 65.61,75.496 65.61,75.304 65.713,75.389 65.735,75.4 65.713,75.411
GND on Bottom (solid): 69.305,75.64 69.294,75.618 69.2,75.505 69.087,75.411 69.065,75.4 69.087,75.389 69.2,75.295 69.294,75.182 69.305,75.16 69.316,75.182 69.41,75.295 69.523,75.389 69.545,75.4 69.523,75.411 69.41,75.505 69.316,75.618
GND on Bottom (solid): 68.035,75.64 68.024,75.618 67.93,75.505 67.817,75.411 67.795,75.4 67.817,75.389 67.93,75.295 68.024,75.182 68.035,75.16 68.046,75.182 68.14,75.295 68.253,75.389 68.275,75.4 68.253,75.411 68.14,75.505 68.046,75.618
GND on Bottom (solid): 66.765,75.64 66.754,75.618 66.66,75.505 66.547,75.411 66.525,75.4 66.547,75.389 66.66,75.295 66.754,75.182 66.765,75.16 66.776,75.182 66.87,75.295 66.983,75.389 67.005,75.4 66.983,75.411 66.87,75.505 66.776,75.618
GND on Bottom (solid): 64.363,76.593 59.02,76.593 59.02,73.069 62.011,70.078 62.021,70.079 62.099,70.071 62.107,70.069 62.103,73.552 62.103,73.553 62.108,73.606 62.123,73.658 62.149,73.705 62.183,73.747 64.173,75.737 64.167,75.748 64.124,75.889 64.11,76.035 64.124,76.181 64.167,76.322 64.236,76.452 64.33,76.565

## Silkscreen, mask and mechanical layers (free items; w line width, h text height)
Top Overlay:
  text "3V3 • SWD • 2L" at 43.4,83.4 h0.48
  text "I2C 0x38 • USB-C UART" at 98.4,83.4 h0.5
  text "MSPM0G3507SPMR + CH340N" at 60.4,29.9 h0.52
  text "AHT20" at 101.4,29.9 h0.55
  text "QUICK CONFIGURE • ADAFRUIT SENSOR" at 76.4,27.4 h0.65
